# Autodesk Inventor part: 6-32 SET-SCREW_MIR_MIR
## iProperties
Created: 2007-08
Part Number: 6-32 SET-SCREW_MIR_MIR
Document SubType Name: Modeling
Mass: 0.0379541 g
Surface Area: 1.01226 cm^2
Volume: 0.0379541 cm^3
Density: 1 g/cm^3
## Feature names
1. Derived Body1 [Tagging]
